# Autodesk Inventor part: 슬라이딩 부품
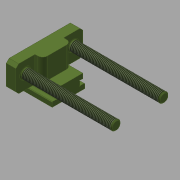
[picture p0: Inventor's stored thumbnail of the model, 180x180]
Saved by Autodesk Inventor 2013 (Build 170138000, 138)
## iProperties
Created: 2017-04
Part Number: 슬라이딩 부품
Material: 강철, 연강
Document SubType Name: Modeling
Designer: mduedu
Density: 7.86 g/cm^3
Mass: 395.304 g
Surface Area: 150.948 cm^2
Volume: 50.2931 cm^3
Author: mduedu
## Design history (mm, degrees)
sketch "스케치1"
  geometry: L1 (37, 35)-(10, 35); L2 (0, 17)-(0, 0); L3 (0, 17)-(5, 17); L4 (5, 17)-(5, 12); L5 (5, 12)-(10, 12); L6 (10, 12)-(10, 35); L7 (37, 35)-(37, 0); L8 (37, 0)-(0, 0); L9 (37, -35)-(10, -35); L10 (0, -17)-(0, 0); L11 (0, -17)-(5, -17); L12 (5, -17)-(5, -12); L13 (5, -12)-(10, -12); L14 (10, -12)-(10, -35); L15 (37, -35)-(37, 0)
  constraints: 30 end point, 6 symmetric about line, 3 perpendicular, 2 horizontal, 2 point on line, 2 vertical
  dimensions: "d39" = 5 distance of L2.start L3.end; "d41" = 70 distance between parallel lines of L9 L1; "d42" = 27 distance of L9.start L9.end; "d43" = 24 distance between parallel lines of L13 L5; "d44" = 5 distance of L4.end L5.end; "d45" = 34 distance between parallel lines of L11 L3
extrude "돌출1" new body sketch "스케치1" distance "d5" = 10; taper "d6" = 0 deg
sketch "스케치2"
  geometry: L1 (-35, 10)-(-35, 37) reference; L2 (17, 0)-(-17, 0) reference; L3 (-17, 0)-(-17, 5) reference; L4 (-17, 5)-(-12, 5) reference; L5 (-12, 5)-(-12, 10) reference; L6 (-12, 10)-(-35, 10) reference; L7 (-35, 37)-(35, 37) reference; L8 (35, 37)-(35, 10) reference; L9 (35, 10)-(12, 10) reference; L10 (12, 10)-(12, 5) reference; L11 (12, 5)-(17, 5) reference; L12 (17, 5)-(17, 0) reference; L13 (-12, 10)-(-15, 10); L14 (-15, 10)-(-15, 15); L15 (-15, 15)-(15, 15); L16 (15, 15)-(15, 10); L17 (15, 10)-(12, 10)
  constraints: 10 end point, 4 perpendicular, 2 point on line
  dimensions: "d46" = 3 distance between parallel lines of L14 L5; "d47" = 3 distance between parallel lines of L16 L10 (= d46); "d48" = 5 distance of L13.end L14.end
extrude "돌출2" join sketch "스케치2" distance "d12" = 20; taper "d13" = 0 deg
sketch "스케치3"
  geometry: L1 (0, 20)-(8, 20); L2 (8, 20)-(8, 50); L3 (8, 50)-(0, 50); L4 (0, 50)-(0, 20); L5 (0, 50)-(20, 50) reference; L6 (0, 20)-(20, 20) reference; L7 (0, 0)-(0, 70) reference; 2 further points
  constraints: 8 end point, 2 midpoint, 2 parallel, 1 horizontal, 1 perpendicular, 1 point on line
  dimensions: "d14" = 8 distance between parallel lines of L2 L4
extrude "돌출3" join sketch "스케치3" stored distance "d16" = 20; taper "d17" = 0 deg
fillet "모깎기1" dims "d18" = 5
sketch "스케치4"
  geometry: L1 (-15, 10)-(-35, 10) reference; L2 (-35, 10)-(-35, 37) reference; C1 r 5 at (-25, 25); 1 further point
  constraints: 1 centre point
  dimensions: "d19" = 10 diameter of C1; "d23" = 25 horizontal distance of point (0, 0) C1.centre (derived); "d49" = 15 distance from line of C1.centre L1; "d50" = 10 distance from line of C1.centre L2
extrude "돌출4" join sketch "스케치4" distance "d24" = 95; taper "d25" = 0 deg
feature "스레드1" dims "d26" = 10, "d27" = 0
chamfer "모따기1" distance "d28" = 1; stored, may be unused: second distance "d29" = 2, angle "d30" = 45 deg
fillet "모깎기2" dims "d31" = 1
sketch "스케치5"
  geometry: L1 (-12, 5)-(-12, 10) reference; L2 (12, 10)-(12, 5) reference; C1 r 0.5 at (-12, 10); C2 r 0.5 at (-12, 5); C3 r 0.5 at (12, 5); C4 r 0.5 at (12, 10); 1 further point
  constraints: 4 centre point, 4 coincident, 3 equal radius
  dimensions: "d51" = 1 diameter of C1
extrude "돌출5" cut sketch "스케치5" stored distance "d34" = 89; taper "d35" = 0 deg
chamfer "모따기2" distance "d36" = 3; stored, may be unused: second distance "d37" = 2, angle "d38" = 45 deg
chamfer "모따기3" distance "d52" = 0.5; stored, may be unused: second distance "d53" = 2, angle "d54" = 45 deg
mirror "대칭2"
node "솔리드2"
node "투영된 루프1"
node "솔리드1"
